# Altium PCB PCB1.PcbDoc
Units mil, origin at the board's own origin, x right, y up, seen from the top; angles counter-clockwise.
Board outline 1574.8 x 1574.8 mil, 2 copper layers (Top Layer, Bottom Layer); 32 components, 18 nets, 69 pads, 13 vias.
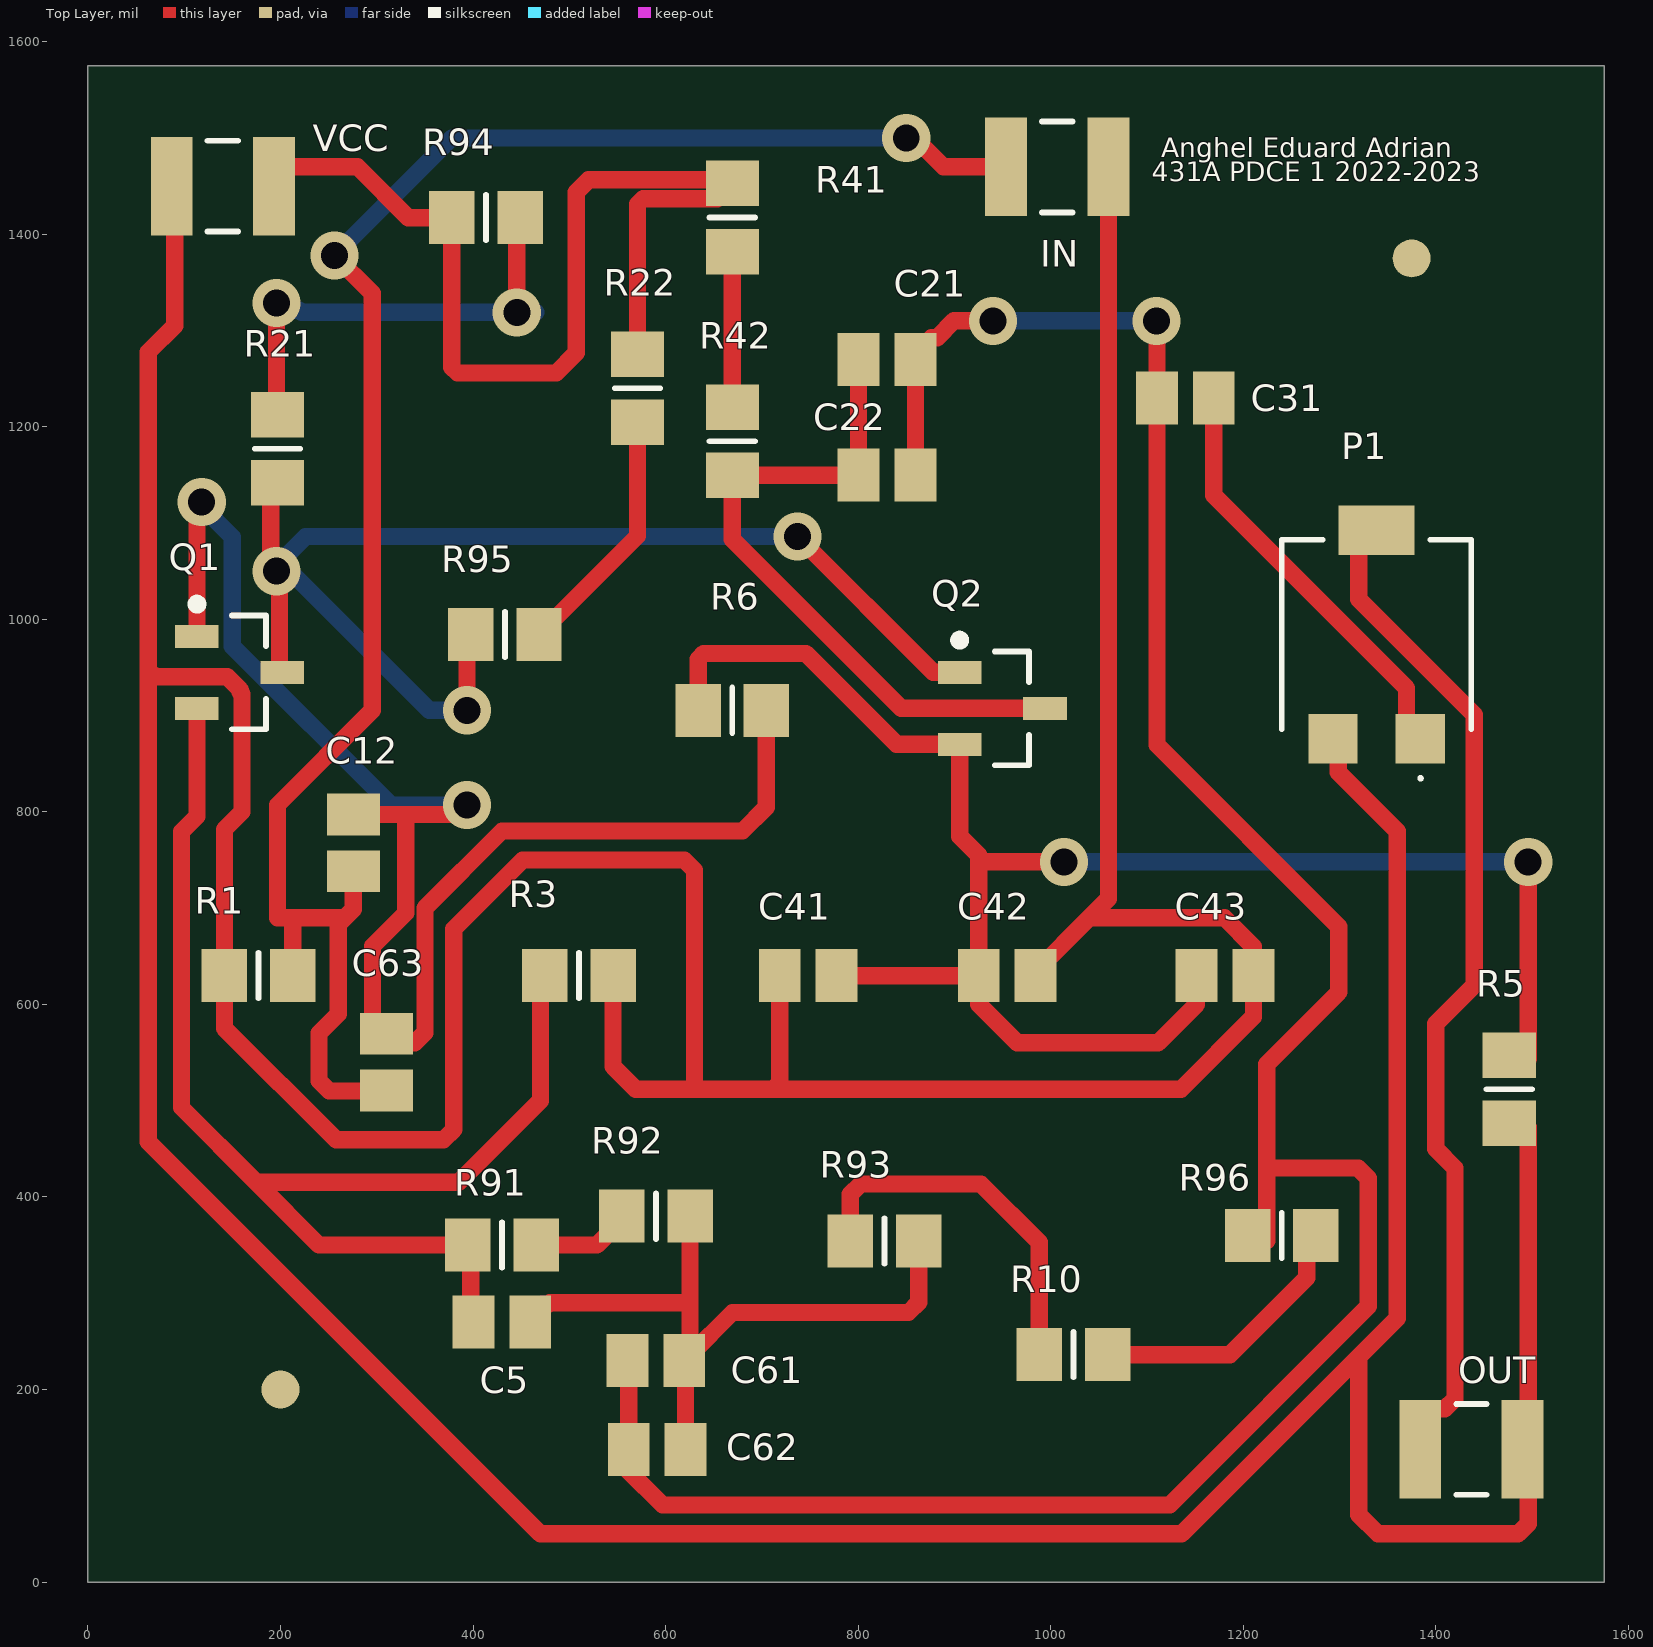
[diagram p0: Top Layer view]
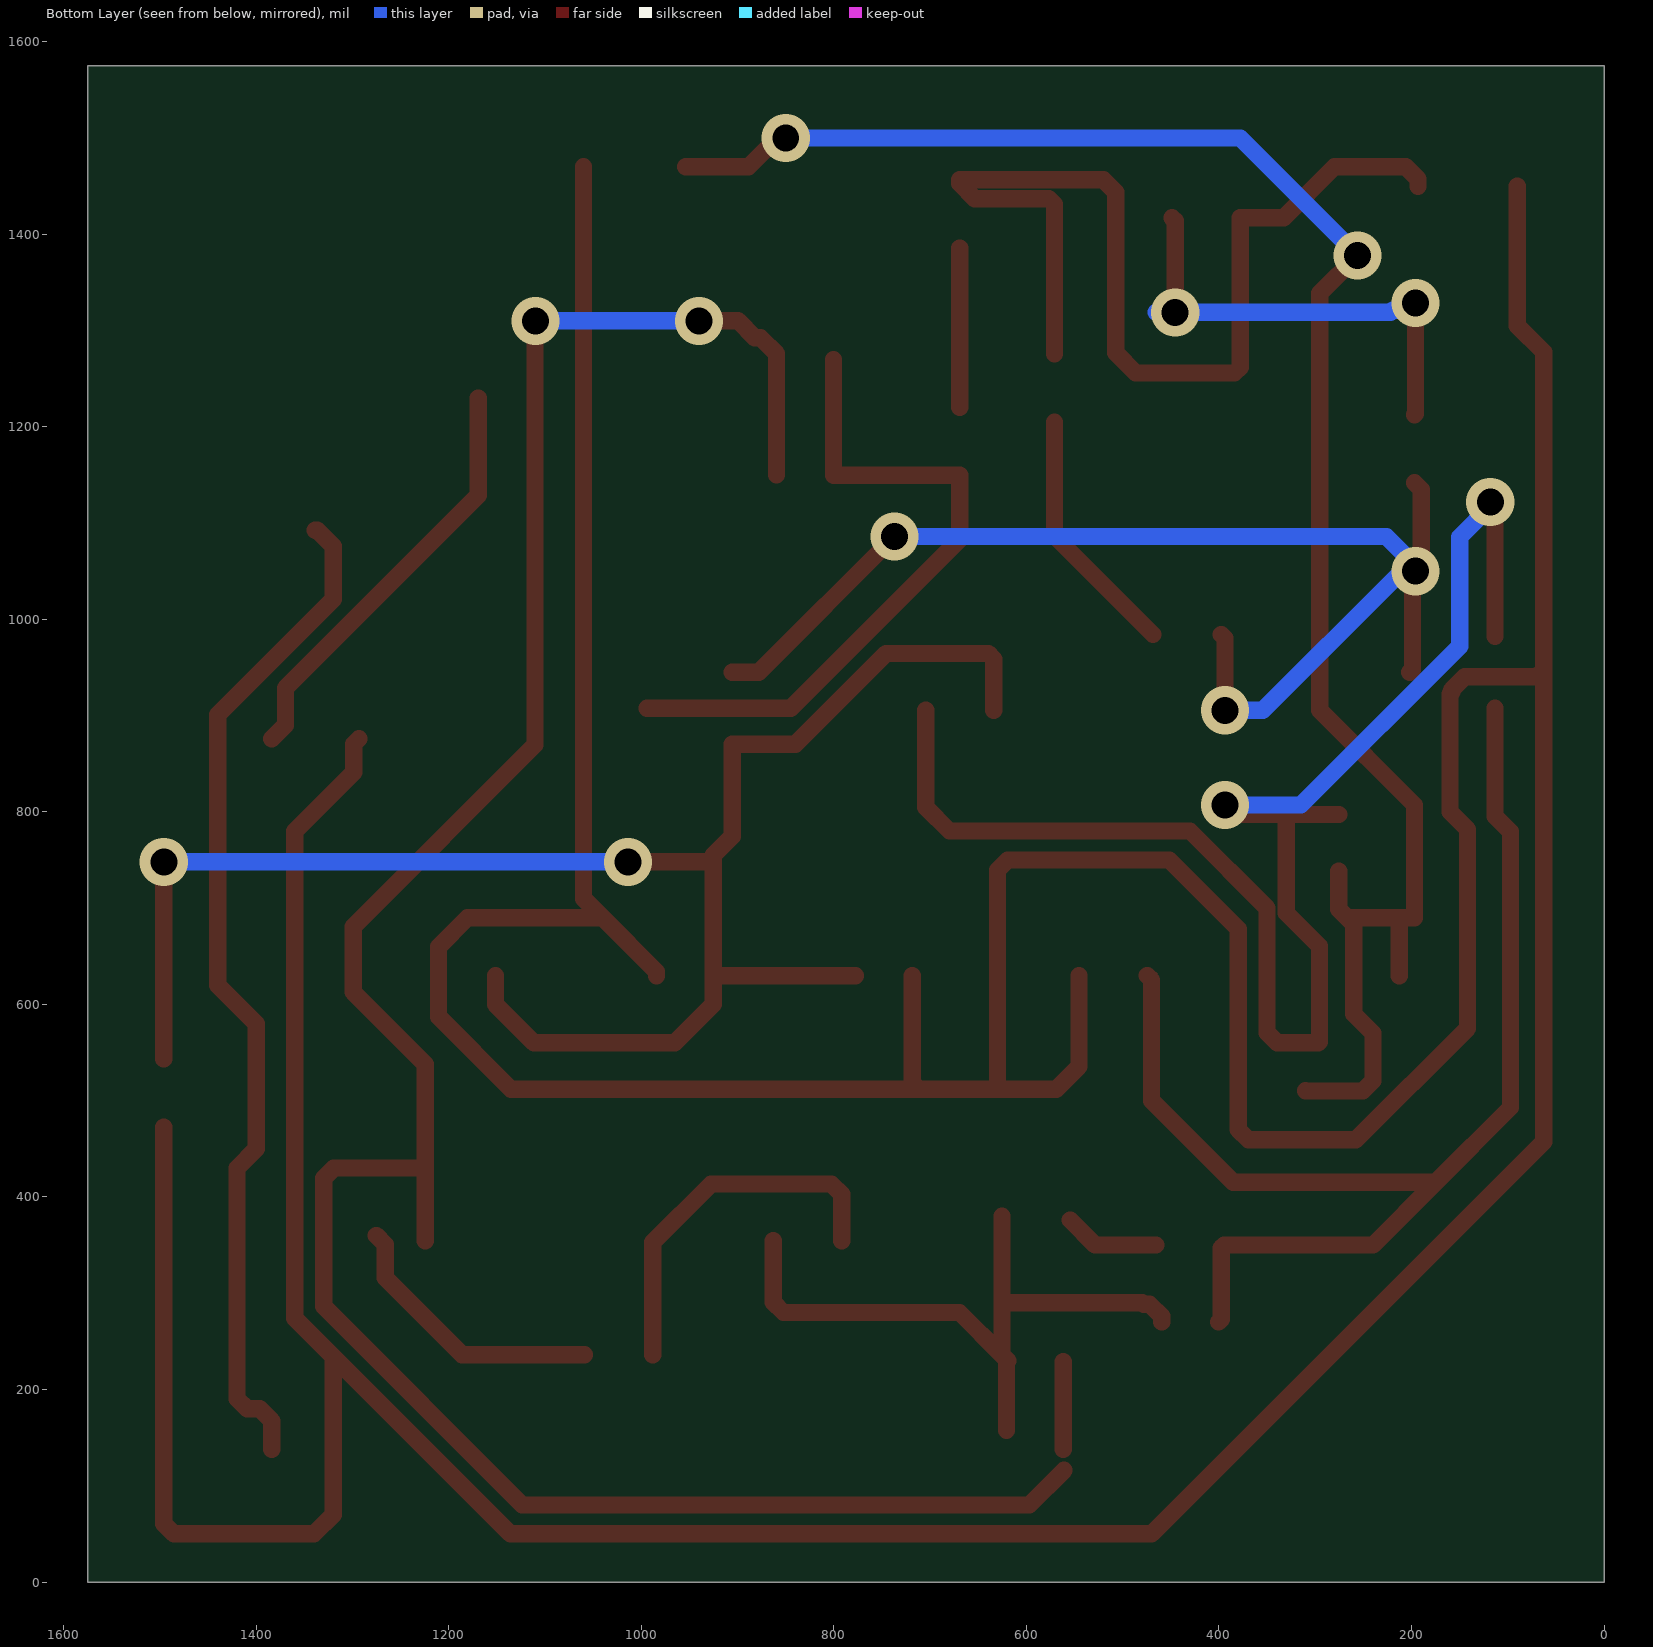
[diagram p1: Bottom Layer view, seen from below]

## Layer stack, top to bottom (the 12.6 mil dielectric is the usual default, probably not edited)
Top Solder: solder mask 0.4, Solder Resist, Dk 3.5
Top Layer: signal copper 1.4
Dielectric 1: dielectric 12.6, FR-4, Dk 4.8
Bottom Layer: signal copper 1.4
Bottom Solder: solder mask 0.4, Solder Resist, Dk 3.5

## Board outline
0,0 1574.8,0 1574.8,1574.8 0,1574.8

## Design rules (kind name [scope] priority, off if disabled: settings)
Clearance [All] p1: gap=12 ignorepadtopadclearanceinfootprint=FALSE except(0: Arc-Hole Track-Hole SMDPad-Hole THPad-Hole Via-Hole Fill-Hole Poly-Hole Region-Hole Text-Hole)
PolygonConnect [All] p1: connectstyle=Relief reliefconductorwidth=10 reliefentries=4 polygonreliefangle="90 Angle" airgapwidth=10
RoutingVias [All] p1: holewidth=28 width=50 viastyle="Through Hole" minholewidth=28 minwidth=50 maxholewidth=28 maxwidth=50
SolderMaskExpansion [All] p1: expansion=4 istentingtop=FALSE
Width [All] p1: maxlimit=18 minlimit=10 preferedwidth=18 minimp=50.000000 maximp=50.000000 favimp=50.000000
30 further rules are at their usual default settings.

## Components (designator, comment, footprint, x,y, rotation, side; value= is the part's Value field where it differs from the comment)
C5 "1n" C0805 430,270 r180 top
C12 "4.7u" C0805 275.59,767.72 r90 top
C21 "4.7u" C0805 830,1270 r0 top
C22 "4.7u" C0805 830,1150 r0 top
C31 "4.7u" C0805 1140,1230 r0 top
C41 "4.7u" C0805 748.03,629.92 r0 top
C42 "4.7u" C0805 954.72,629.92 r180 top
C43 "4.7u" C0805 1181.1,629.92 r180 top
C61 "2.2n" C0805 590,230 r0 top
C62 "1n" C0805 591.18,137.8 r0 top
C63 "4.7u" C0805 310,540 r90 top
IN "Header 2" C1210 1006.85,1470 r0 top
OUT "Header 2" C1210 1437.01,137.8 r0 top
P1 "Potentiometer" TS53YL104MR10 1338.58,984.25 r0 top value=5K
Q1 "QBC846B" SOT-23_N 157.48,944.88 r0 top
Q2 "QBC846B" SOT-23_N 949.8,907.48 r0 top
R1 "47k" 6-0805_N 177.17,629.92 r0 top
R3 "1k" 6-0805_N 510,630 r180 top
R5 "1k" 6-0805_N 1476.38,511.81 r90 top
R6 "510k" 6-0805_N 669.29,905.51 r0 top
R10 "390k" 6-0805_N 1023.62,236.22 r0 top
R21 "330k" 6-0805_N 196.85,1177.17 r90 top
R22 "330k" 6-0805_N 570.87,1240.16 r90 top
R41 "10k" 6-0805_N 669.29,1417.32 r90 top
R42 "5.6k" 6-0805_N 669.29,1185.04 r90 top
R91 "68k" 6-0805_N 430,350 r0 top
R92 "22k" 6-0805_N 590,380 r0 top
R93 "510k" 6-0805_N 827.4,354.33 r180 top
R94 "68k" 6-0805_N 413.39,1417.32 r180 top
R95 "68k" 6-0805_N 433.07,984.25 r0 top
R96 "100k" 6-0805_N 1240,360 r180 top
VCC "Header 2" C1210 140,1450 r180 top

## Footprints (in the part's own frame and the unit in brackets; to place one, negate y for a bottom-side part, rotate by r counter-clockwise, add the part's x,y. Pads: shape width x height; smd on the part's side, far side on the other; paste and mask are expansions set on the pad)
6-0805_N [mm] "Chip Resistor, Body 2.0x1.2mm, IPC Medium Density"
  rect 1.2x1.4 smd: 1(-0.9,0) 2(0.9,0)
  silkscreen extent 0,-0.6 0,0.6, body extent -1.07,-0.7 1.07,0.7, height 0.7
C0805 [mm] "Chip Capacitor, Body 2.0x1.3mm, IPC High Density"
  rect 1.1x1.4 smd: 1(-0.75,0) 2(0.75,0)
  body extent -1.1,-0.72 1.1,0.72, height 1.4
C1210 [mm] "Chip Capacitor, Body 3.2x2.5mm, IPC High Density"
  rect 1.1x2.6 smd: 1(-1.35,0) 2(1.35,0)
  silkscreen extent -0.4,-1.2 0.4,1.2, body extent -1.7,-1.35 1.7,1.35, height 1.3
SOT-23_N [mm] "SOT23, 3-Leads, Body 2.9x1.3mm, Pitch 0.95mm, Lead Span 2.5mm, IPC Medium Density"
  rect 1.15x0.6 smd: 1(-1.125,0.95) 2(-1.125,-0.95) 3(1.125,0)
  silkscreen extent -1.25,-1.5 0.7,1.92, body extent -0.7,-1.5 0.7,1.5, height 1.1
TS53YL104MR10 [mm]
  rect 1.3x1.3 smd: A1(1.15,-2.75) C1(-1.15,-2.75)
  rect 2x1.3 smd: B1(0,2.75)
  silkscreen extent -2.5,-3.84 2.5,2.5, body extent -3.7,-3.99 3.77,3.81, height 3.52

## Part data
C5 C12 C21 C22 C31 C41 C42 C43 C61 C62 C63: library part C, CURRENT=CIMAX, MAX_TEMP=CTMAX, PSpiceTemplate="C^@REFDES %1 %2 ?TOLERANCE[]C^@REFDES[] @VALUE ?IC/IC{}@IC/ TC{}@TC1,@TC2 ?TOLERANCE[]\n.model C^@REFDES CAP C{}1 DEV{}@TOLERANCE% TC1{}@TC1 TC2{}@TC2 VC1{}@VC1 VC2{}@VC2[]", VOLTAGE=CMAX
IN OUT VCC: "Header, 2-Pin"
Q1 Q2: PSpiceTemplate="Q^@REFDES %C %B %E @MODEL ?AREA/@AREA/"
R1 R10 R91 R92: library part R, BiasValue Power=0W, MAX_TEMP=RTMAX, POWER=RMAX, PSpiceTemplate="R^@REFDES %1 %2 ?TOLERANCE[]R^@REFDES[] @VALUE TC{}@TC1,@TC2 ?TOLERANCE[]\n.model R^@REFDES RES R{}1 DEV{}@TOLERANCE% TC1{}@TC1 TC2{}@TC2[]", VOLTAGE=RVMAX
R3 R5 R6 R21 R22 R41 R42: library part R, MAX_TEMP=RTMAX, POWER=RMAX, PSpiceTemplate="R^@REFDES %1 %2 ?TOLERANCE[]R^@REFDES[] @VALUE TC{}@TC1,@TC2 ?TOLERANCE[]\n.model R^@REFDES RES R{}1 DEV{}@TOLERANCE% TC1{}@TC1 TC2{}@TC2[]", VOLTAGE=RVMAX
R93 R96: library part RESISTOR, BiasValue Power=0W, MAX_TEMP=RTMAX, POWER=RMAX, VOLTAGE=RVMAX
R94 R95: library part RESISTOR, MAX_TEMP=RTMAX, POWER=RMAX, VOLTAGE=RVMAX

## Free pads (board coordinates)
  round 39.37 smd mask+39.37: 1(200,200) 3(1375,1375)

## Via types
v1: diameter 50, hole 28, Top Layer to Bottom Layer, 13 vias

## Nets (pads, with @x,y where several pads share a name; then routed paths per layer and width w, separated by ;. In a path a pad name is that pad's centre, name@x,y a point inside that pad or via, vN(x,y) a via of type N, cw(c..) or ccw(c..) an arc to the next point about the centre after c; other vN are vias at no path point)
GND: C41.1 C42.1 C43.1 IN.2 OUT.2 P1.C1 R1.1 R3.1 R5.1 VCC.2 | length 7480.3
  Top Layer w18: VCC.2@90,1450 90,1305 62.68,1277.68 62.68,947.32 ; R3.1 545.43,535.43 569.06,511.81 630,511.81 ; C41.1 718.5,518.5 711.81,511.81 ; C42.1 984.25,634 1040.25,690 ; IN.2 1060,709.75 1040.25,690 ; P1.C1 1298.75,870.54 1298.75,841.25 1360,780 1360,274.01 1320,234.01 ; R5.1@1496.06,472.44 1496.06,60.54 1485.52,50 1340,50 1320,70 1320,234.01 ; 62.68,947.32 62.68,940.29 62.68,457.32 470,50 1135.99,50 1320,234.01 ; 62.68,947.32 69.71,940.29 144.52,940.29 158.13,926.68 158.13,924.37 160,922.51 160,800 141.73,781.73 R1.1 141.73,575.36 257.78,459.32 369.32,459.32 380,470 380,678.33 451.67,750 619.46,750 630,739.46 630,511.81 ; 630,511.81 711.81,511.81 ; 711.81,511.81 1135.44,511.81 1210.63,587 C43.1 1210.63,660 1180.63,690 1040.25,690
IN: C12.1 C63.1 IN.1 R1.2 | length 1939.5
  Top Layer w18: 196.85,690 196.85,807.09 295.28,905.51 295.28,1338.58 v1(255.91,1377.95) ; 200,690 212.6,690 ; R1.2 212.6,690 ; C12.1 275.59,698.82 266.77,690 ; C63.1 309.53,510 250.76,510 240,520.76 240,570 260,590 260,683.23 266.77,690 ; v1(850,1500) 858.66,1500 888.66,1470 IN.1 ; 212.6,690 266.77,690
  Bottom Layer w18: v1(255.91,1377.95) 377.95,1500 v1(850,1500)
NetC5_1: C5.1 C61.2 C62.2 R92.2 R93.1 | length 727.6
  Top Layer w18: C5.1 459.53,275.91 472.18,288.56 478.09,288.56 479.53,290 625.43,290 ; C62.2@620.71,157.48 620.71,230 C61.2 C61.2@625.43,235.91 ; R92.2 625.43,290 ; R93.1 862.83,290.54 852.29,280 669.53,280 C61.2@625.43,235.91 ; C61.2@625.43,235.91 625.43,290
NetC5_2: C5.2 Q1.2 R3.2 R91.1 | length 1322.5
  Top Layer w18: Q1.2 113.19,795.61 97.11,779.54 97.11,492.89 174.81,415.19 ; C5.2 397.52,272.95 397.52,347.05 R91.1 240,350 174.81,415.19 ; R3.2 470,625.43 470,500 385.19,415.19 174.81,415.19
NetC12_2: C12.2 C63.2 Q1.1 R6.2 | length 1729.1
  Top Layer w18: Q1.1 113.19,1117.13 v1(118.11,1122.05) ; v1(393.7,807.09) 385.04,807.09 375.2,797.25 330,797.25 C12.2 326.08,797.25 330,793.33 330,695 295.59,660.59 295.59,561.34 296.93,560 339.46,560 350,570.54 350,700 430.08,780.08 679.92,780.08 704.72,804.88 R6.2
  Bottom Layer w18: v1(118.11,1122.05) 118.11,1117.39 150,1085.5 150,972.05 314.96,807.09 v1(393.7,807.09)
NetC21_1: C21.1 C22.1 Q2.3 R42.1 | length 715.4
  Top Layer w18: C21.1 C22.1 800.08,1149.61 R42.1 669.29,1083.13 844.95,907.48 Q2.3
NetC21_2: C21.2 C22.2 C31.1 C61.1 C62.1 R96.2 | length 2669.1
  Top Layer w18: C62.1@560.88,116.12 597,80 1123.56,80 1330,286.44 1330,419.46 1319.46,430 1224.41,430 ; C62.1 C61.1@561.65,228.82 ; C22.2 C21.2 859.53,1275.9 876.18,1292.56 882.09,1292.56 899.53,1310 v1(940,1310) v1@950,1310 ; v1(1110,1310) 1110.47,1309.53 C31.1 1110.47,869.53 1299.21,680.79 1299.21,612.8 1224.41,538 1224.41,430 ; R96.2@1224.41,354.33 1224.41,430
  Bottom Layer w18: v1(940,1310) v1(1110,1310)
NetC31_2: C31.2 P1.A1 | length 442.8
  Top Layer w18: C31.2 1169.53,1128.77 1369.72,928.57 1369.72,890.12 P1.A1
NetC41_2: C41.2 C42.2 C43.2 Q2.2 R5.2 R6.1 | length 1857.3
  Top Layer w18: R6.1 633.86,958.71 639.72,964.57 745.43,964.57 839.92,870.08 Q2.2 905.51,774.49 925.2,754.8 C42.2 ; C41.2 C42.2 ; 925.2,748.03 v1(1014,748.03) ; C43.2 1151.57,600 1111.57,560 965.2,560 925.2,600 C42.2 ; R5.2@1496.06,543.31 v1(1496.06,748.03)
  Bottom Layer w18: v1(1014,748.03) v1(1496.06,748.03)
NetQ1_3: Q1.3 Q2.1 R21.1 R95.1 | length 1328.9
  Top Layer w18: v1@190,1050 190,1134.88 R21.1 ; v1(196,1050) 198.89,1047.11 198.89,947.69 201.7,944.88 Q1.3 ; v1(393.7,905.51) 393.7,980.32 R95.1 ; v1(737,1086) 878.12,944.88 Q2.1
  Bottom Layer w18: v1@190,1050 226,1086 v1(737,1086) ; v1(196,1050) 202.12,1043.88 216.12,1043.88 354.49,905.51 v1(393.7,905.51)
NetR10_1: R10.1 R93.2 | length 390.8
  Top Layer w18: R93.2 791.97,402.84 802.51,413.39 927.61,413.39 988.19,352.81 R10.1
NetR10_2: R10.2 R96.1 | length 287.9
  Top Layer w18: R10.2 1186.22,236.22 1266.03,316.03 1266.03,350.6 R96.1
NetR21_2: R21.2 R94.1 | length 489.7
  Top Layer w18: v1(195.88,1328.74) 195.88,1213.57 R21.2 ; v1(445.44,1318.9) 445.44,1413.94 R94.1
  Bottom Layer w18: v1(195.88,1328.74) 203.54,1321.08 219.55,1321.08 221.74,1318.9 v1@465.13,1318.9
NetR22_1: R22.1 R95.2 | length 262.9
  Top Layer w18: R95.2 570.87,1086.61 R22.1
NetR41_1: R41.1 R42.2 | length 165.4
  Top Layer w18: R42.2 R41.1@669.29,1385.83
NetR91_2: R91.2 R92.1 | length 99.9
  Top Layer w18: R91.2 528.5,350 R92.1@554.57,376.06
OUT: OUT.1 P1.B1 | length 1060.7
  Top Layer w18: P1.B1 1336.59,1092.52 1320,1075.93 1320,1020.72 1440,900.72 1440,620 1400,580 1400,450 1420,430 1420,190.52 1409.46,179.98 1396.51,179.98 1383.86,167.32 OUT.1
VCC: R22.2 R41.2 R94.2 VCC.1 | length 1112.5
  Top Layer w18: VCC.1 193.15,1457.35 205.8,1470 280,1470 332.68,1417.32 R94.2 377.95,1261.76 383.81,1255.91 486.27,1255.91 507.13,1276.76 507.13,1443.82 520,1456.69 R41.2@669.29,1456.69 ; R22.2 570.87,1431.15 576.72,1437.01 653.54,1437.01 R41.2

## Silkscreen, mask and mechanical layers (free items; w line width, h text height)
Top Overlay:
  text "Anghel Eduard Adrian" at 1115,1480 h20
  text "431A PDCE 1 2022-2023" at 1105,1455 h20
Mechanical 1:
  lines w1: 39.37,39.37 1535.43,39.37 1535.43,1535.43 39.37,1535.43 39.37,39.37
